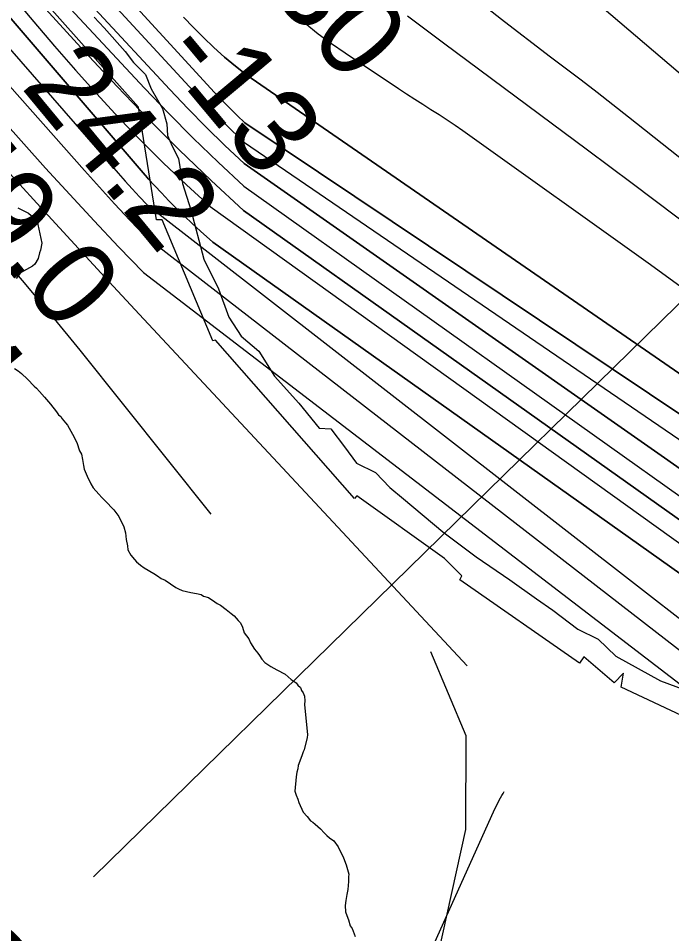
# Model space of a CAD drawing. Extents: x 3172231 to 3210228, y 940198 to 965780.
# Drawn here: x 3190904 to 3191420, y 947104 to 947827 of the extents above; entities that cross this region are included whole.
import ezdxf

# ---------------------------------------------------------------- set-up
doc = ezdxf.new("R2010")
doc.units = 0
for name, color, linetype in [('V-RIVR-EDGE', 7, 'Continuous'), ('V-RIVR-RANG', 7, 'Continuous'), ('V-RIVR-RANG-IDEN', 7, 'Continuous'), ('V-ROAD-CNTR', 7, 'Continuous'), ('V-RRAP-RVMT', 7, 'Continuous'), ('V-SITE-VEGE', 7, 'Continuous'), ('V-TOPO-DPTH', 7, 'Continuous'), ('V-TOPO-MAJR', 7, 'Continuous'), ('V-TOPO-MINR', 7, 'Continuous'), ('V-TOPO-SHOR', 7, 'Continuous'), ('V-TOPO-WATR', 7, 'Continuous')]:
    doc.layers.add(name, color=color, linetype=linetype)

msp = doc.modelspace()

# ---------------------------------------------------------------- linework, layer by layer
at = {"layer": 'V-RIVR-EDGE'}
msp.add_lwpolyline([(3190963.675, 947827.885), (3190971.434, 947819.568), (3190987.984, 947800.857), (3190994.704, 947792.023), (3191004.016, 947782.665), (3191008.656, 947771.244), (3191017.434, 947755.664), (3191021.034, 947743.726), (3191021.53, 947734.39), (3191025.14, 947726.083), (3191030.302, 947716.216), (3191033.365, 947696.501), (3191040.055, 947675.74), (3191050.332, 947636.818), (3191061.684, 947613.452), (3191069.926, 947591.13), (3191079.743, 947576.066), (3191093.716, 947564.103), (3191106.114, 947544.365), (3191125.251, 947523.054), (3191141.279, 947503.307), (3191150.613, 947502.765), (3191161.469, 947488.735), (3191170.772, 947475.747), (3191185.794, 947468.449), (3191197.175, 947456.492), (3191208.044, 947447.649), (3191239.097, 947421.641), (3191265.498, 947401.868), (3191291.902, 947383.651), (3191313.129, 947368.558), (3191326.072, 947359.71), (3191345.743, 947344.621), (3191361.801, 947336.802), (3191375.77, 947323.283), (3191410.989, 947304.007), (3191430.16, 947296.699)], dxfattribs=at)
at = {"layer": 'V-RIVR-RANG'}
msp.add_line((3190962.933, 947149.209), (3191771.579, 947939.938), dxfattribs=at)
at = {"layer": 'V-ROAD-CNTR'}
msp.add_lwpolyline([(3191038.305, 946665.928), (3191279.107, 947200.55), (3191279.971, 947202.406), (3191280.86, 947204.251), (3191281.776, 947206.084), (3191282.716, 947207.905), (3191283.682, 947209.713), (3191284.673, 947211.509), (3191285.689, 947213.291), (3191286.73, 947215.058), (3191287.616, 947216.523)], dxfattribs=at)
at = {"layer": 'V-RRAP-RVMT'}
for p, q in [((3190998.585, 947756.725), (3190913.183, 947852.785)), ((3191012.785, 947667.841), (3190998.585, 947756.725)), ((3191017.206, 947667.92), (3191012.785, 947667.841)), ((3191057.359, 947572.274), (3191017.206, 947667.92)), ((3191059.556, 947572.991), (3191057.359, 947572.274)), ((3191169.285, 947447.752), (3191059.556, 947572.991)), ((3191171.22, 947449.949), (3191169.285, 947447.752)), ((3191240.29, 947400.509), (3191171.22, 947449.949)), ((3191254.065, 947386.827), (3191240.29, 947400.509)), ((3191252.577, 947383.56), (3191254.065, 947386.827)), ((3191347.149, 947317.821), (3191252.577, 947383.56)), ((3191350.507, 947322.991), (3191347.149, 947317.821)), ((3191374.555, 947302.305), (3191350.507, 947322.991)), ((3191381.916, 947309.92), (3191374.555, 947302.305)), ((3191379.902, 947299.004), (3191381.916, 947309.92)), ((3191508.358, 947238.465), (3191379.902, 947299.004))]:
    msp.add_line(p, q, dxfattribs=at)
at = {"layer": 'V-SITE-VEGE'}
for p, q in [((3190903.338, 947677.339), (3190911.675, 947673.106)), ((3190911.675, 947673.106), (3190913.834, 947671.222)), ((3190913.834, 947671.222), (3190916.341, 947668.594)), ((3190916.341, 947668.594), (3190919.171, 947664.125)), ((3190919.171, 947664.125), (3190921.477, 947653.064)), ((3190922.124, 947649.382), (3190921.262, 947643.897)), ((3190921.477, 947653.064), (3190922.124, 947649.382)), ((3190920.478, 947641.714), (3190919.275, 947637.34)), ((3190921.262, 947643.897), (3190920.478, 947641.714)), ((3190916.605, 947632.998), (3190914.727, 947631.208)), ((3190919.275, 947637.34), (3190916.605, 947632.998)), ((3190905.431, 947625.926), (3190902.027, 947621.603)), ((3190914.727, 947631.208), (3190905.431, 947625.926)), ((3190900.723, 947550.457), (3190903.612, 947548.555)), ((3190903.612, 947548.555), (3190906.136, 947546.66)), ((3190906.136, 947546.66), (3190910.801, 947542.148)), ((3190910.801, 947542.148), (3190916.171, 947536.519)), ((3190916.171, 947536.519), (3190917.971, 947535.007)), ((3190917.971, 947535.007), (3190920.476, 947532.382)), ((3190920.476, 947532.382), (3190924.408, 947527.886)), ((3190924.408, 947527.886), (3190929.044, 947522.277)), ((3190929.044, 947522.277), (3190933.673, 947516.295)), ((3190933.673, 947516.295), (3190935.455, 947514.052)), ((3190935.455, 947514.052), (3190937.257, 947512.543)), ((3190937.257, 947512.543), (3190938.312, 947510.683)), ((3190938.312, 947510.683), (3190940.808, 947507.689)), ((3190940.808, 947507.689), (3190942.598, 947505.813)), ((3190942.598, 947505.813), (3190946.469, 947498.751)), ((3190946.469, 947498.751), (3190949.981, 947492.065)), ((3190949.981, 947492.065), (3190952.025, 947485.413)), ((3190952.025, 947485.413), (3190953.432, 947482.812)), ((3190953.432, 947482.812), (3190954.438, 947478.753)), ((3190954.438, 947478.753), (3190955.06, 947473.964)), ((3190955.06, 947473.964), (3190955.724, 947471.017)), ((3190955.724, 947471.017), (3190958.161, 947465.457)), ((3190958.161, 947465.457), (3190960.956, 947459.52)), ((3190960.956, 947459.52), (3190962.712, 947456.178)), ((3190962.712, 947456.178), (3190967.367, 947451.297)), ((3190967.367, 947451.297), (3190969.507, 947448.68)), ((3190969.507, 947448.68), (3190972.38, 947446.044)), ((3190972.38, 947446.044), (3190979.182, 947438.913)), ((3190979.182, 947438.913), (3190983.095, 947433.684)), ((3190983.095, 947433.684), (3190984.834, 947429.609)), ((3190984.834, 947429.609), (3190985.895, 947427.749)), ((3190985.895, 947427.749), (3190986.939, 947425.523)), ((3190986.939, 947425.523), (3190988.295, 947420.72)), ((3190988.295, 947420.72), (3190988.907, 947415.57)), ((3190988.907, 947415.57), (3190989.886, 947410.411)), ((3190989.886, 947410.411), (3190990.185, 947407.47)), ((3190990.185, 947407.47), (3190992.647, 947403.007)), ((3190992.647, 947403.007), (3190995.504, 947399.638)), ((3190995.504, 947399.638), (3190996.925, 947397.771)), ((3190996.925, 947397.771), (3191000.167, 947395.127)), ((3191000.167, 947395.127), (3191003.057, 947393.224)), ((3191003.057, 947393.224), (3191010.655, 947388.643)), ((3191010.655, 947388.643), (3191013.547, 947386.742)), ((3191013.547, 947386.742), (3191016.437, 947384.837)), ((3191016.437, 947384.837), (3191019.701, 947383.293)), ((3191019.701, 947383.293), (3191028.006, 947377.596)), ((3191028.006, 947377.596), (3191030.181, 947376.445)), ((3191030.181, 947376.445), (3191033.089, 947375.275)), ((3191033.089, 947375.275), (3191040.021, 947373.643)), ((3191040.021, 947373.643), (3191044.404, 947372.808)), ((3191044.404, 947372.808), (3191048.054, 947371.988)), ((3191048.054, 947371.988), (3191049.86, 947370.848)), ((3191049.86, 947370.848), (3191053.868, 947369.65)), ((3191053.868, 947369.65), (3191058.924, 947366.229)), ((3191058.924, 947366.229), (3191060.733, 947365.087)), ((3191060.733, 947365.087), (3191063.264, 947363.559)), ((3191063.264, 947363.559), (3191067.954, 947360.147)), ((3191067.954, 947360.147), (3191071.919, 947357.12)), ((3191071.919, 947357.12), (3191074.076, 947355.234)), ((3191074.076, 947355.234), (3191077.291, 947351.49)), ((3191077.291, 947351.49), (3191079.081, 947349.612)), ((3191079.081, 947349.612), (3191080.836, 947346.27)), ((3191080.836, 947346.27), (3191082.2, 947341.836)), ((3191082.2, 947341.836), (3191085.753, 947336.982)), ((3191085.753, 947336.982), (3191087.152, 947334.012)), ((3191087.152, 947334.012), (3191090.333, 947328.802)), ((3191090.333, 947328.802), (3191092.831, 947325.808)), ((3191092.831, 947325.808), (3191094.252, 947323.94)), ((3191094.252, 947323.94), (3191096.018, 947320.964)), ((3191096.018, 947320.964), (3191098.527, 947318.337)), ((3191098.527, 947318.337), (3191103.223, 947315.292)), ((3191103.223, 947315.292), (3191107.929, 947312.613)), ((3191107.929, 947312.613), (3191114.452, 947309.158)), ((3191114.452, 947309.158), (3191119.123, 947305.013)), ((3191119.123, 947305.013), (3191123.099, 947302.35)), ((3191123.099, 947302.35), (3191124.52, 947300.482)), ((3191124.52, 947300.482), (3191126.674, 947298.596)), ((3191126.674, 947298.596), (3191127.358, 947296.38)), ((3191127.358, 947296.38), (3191128.784, 947294.512)), ((3191128.784, 947294.512), (3191129.822, 947291.92)), ((3191130.103, 947288.242), (3191129.667, 947285.319)), ((3191129.667, 947285.319), (3191132.04, 947261.415)), ((3191129.822, 947291.92), (3191130.103, 947288.242)), ((3191131.989, 947259.215), (3191129.556, 947249.366)), ((3191132.04, 947261.415), (3191131.989, 947259.215)), ((3191129.556, 947249.366), (3191128.788, 947247.916)), ((3191127.61, 947244.642), (3191124.864, 947237.003)), ((3191128.788, 947247.916), (3191127.61, 947244.642)), ((3191124.436, 947234.445), (3191123.641, 947231.895)), ((3191124.864, 947237.003), (3191124.436, 947234.445)), ((3191123.191, 947228.235), (3191122.189, 947216.885)), ((3191123.641, 947231.895), (3191123.191, 947228.235)), ((3191122.189, 947216.885), (3191123.211, 947213.559)), ((3191123.211, 947213.559), (3191124.61, 947210.592)), ((3191124.61, 947210.592), (3191125.282, 947208.007)), ((3191125.282, 947208.007), (3191128.767, 947200.223)), ((3191128.767, 947200.223), (3191131.991, 947196.841)), ((3191131.991, 947196.841), (3191134.479, 947193.483)), ((3191134.479, 947193.483), (3191136.288, 947192.342)), ((3191136.288, 947192.342), (3191138.088, 947190.83)), ((3191138.088, 947190.83), (3191142.401, 947187.06)), ((3191142.401, 947187.06), (3191145.264, 947184.058)), ((3191145.264, 947184.058), (3191147.414, 947181.807)), ((3191147.414, 947181.807), (3191149.571, 947179.921)), ((3191149.571, 947179.921), (3191152.819, 947177.643)), ((3191152.819, 947177.643), (3191156.374, 947172.79)), ((3191156.374, 947172.79), (3191160.577, 947164.254)), ((3191160.577, 947164.254), (3191162.648, 947158.701)), ((3191162.648, 947158.701), (3191164.675, 947151.314)), ((3191164.624, 947149.115), (3191164.538, 947145.449)), ((3191164.675, 947151.314), (3191164.624, 947149.115)), ((3191164.538, 947145.449), (3191164.024, 947139.223)), ((3191163.196, 947135.207), (3191162.351, 947130.457)), ((3191164.024, 947139.223), (3191163.196, 947135.207)), ((3191162.351, 947130.457), (3191161.89, 947126.431)), ((3191161.89, 947126.431), (3191162.144, 947121.657)), ((3191162.144, 947121.657), (3191163.174, 947118.698)), ((3191163.174, 947118.698), (3191164.564, 947115.364)), ((3191164.564, 947115.364), (3191165.918, 947110.561)), ((3191165.918, 947110.561), (3191167.333, 947108.327)), ((3191167.333, 947108.327), (3191169.754, 947102.033))]:
    msp.add_line(p, q, dxfattribs=at)
at = {"layer": 'V-TOPO-DPTH'}
for points in [[(3191975.853, 946999.192), (3191057.366, 947650.198), (3191047.698, 947658.964), (3191041.097, 947664.995), (3191034.835, 947670.857), (3191028.67, 947676.816), (3191022.65, 947682.921), (3191016.726, 947689.124), (3191006.307, 947700.299), (3191005.67, 947700.991), (3191003.798, 947703.104), (3190371.389, 948440.144)], [(3190795.989, 948054.391), (3191058.755, 947768.507), (3191064.568, 947762.315), (3191070.468, 947756.208), (3191076.496, 947750.229), (3191082.61, 947744.334), (3191635.142, 947374.634), (3191679.916, 947341.25), (3191724.064, 947307.079), (3191767.273, 947271.729), (3191809.857, 947235.592), (3192012.278, 947059.062), (3192038.925, 947035.354), (3192065.252, 947011.301), (3192091.097, 946986.732), (3192116.621, 946961.819), (3192125.015, 946953.462)], [(3192125.015, 946953.462), (3192116.621, 946961.819), (3192091.097, 946986.732), (3192065.252, 947011.301), (3192038.925, 947035.354), (3192012.278, 947059.062), (3191809.857, 947235.592), (3191767.273, 947271.729), (3191724.064, 947307.079), (3191679.916, 947341.25), (3191635.142, 947374.634), (3191082.61, 947744.334), (3191076.496, 947750.229), (3191070.468, 947756.208), (3191064.568, 947762.315), (3191058.755, 947768.507), (3190795.989, 948054.391)], [(3192105.596, 946941.56), (3192084.673, 946962.391), (3192067.073, 946979.569), (3192049.253, 946996.51), (3192031.1, 947013.095), (3192012.726, 947029.442), (3191871.98, 947152.187), (3191843.196, 947176.588), (3191813.973, 947200.437), (3191784.094, 947223.457), (3191753.777, 947245.924), (3191722.828, 947267.51), (3191691.477, 947288.475), (3191659.523, 947308.509), (3191081.962, 947712.367), (3191066.909, 947726.551), (3191052.087, 947740.967), (3191037.61, 947755.73), (3191023.364, 947770.724), (3190904.893, 947898.407)], [(3190904.893, 947898.407), (3191023.364, 947770.724), (3191037.61, 947755.73), (3191052.087, 947740.967), (3191066.909, 947726.551), (3191081.962, 947712.367), (3191659.523, 947308.509), (3191691.477, 947288.475), (3191722.828, 947267.51), (3191753.777, 947245.924), (3191784.094, 947223.457), (3191813.973, 947200.437), (3191843.196, 947176.588), (3191871.98, 947152.187), (3192012.726, 947029.442), (3192031.1, 947013.095), (3192049.253, 946996.51), (3192067.073, 946979.569), (3192084.673, 946962.391), (3192105.596, 946941.56)], [(3192074.996, 946940.791), (3192052.727, 946962.962), (3192043.051, 946972.406), (3192033.254, 946981.719), (3192023.275, 946990.837), (3192013.173, 946999.824), (3191935.175, 947067.846), (3191919.66, 947080.985), (3191903.9, 947093.815), (3191887.774, 947106.182), (3191871.403, 947118.239), (3191854.676, 947129.792), (3191837.719, 947140.985), (3191820.416, 947151.636), (3191081.606, 947675.34), (3191055.894, 947699.044), (3191030.612, 947723.186), (3191005.973, 947747.984), (3190981.764, 947773.22), (3190956.043, 947800.747), (3190919.634, 947840.373)], [(3190919.634, 947840.373), (3190956.043, 947800.747), (3190981.764, 947773.22), (3191005.973, 947747.984), (3191030.612, 947723.186), (3191055.894, 947699.044), (3191081.606, 947675.34), (3191820.416, 947151.636), (3191837.719, 947140.985), (3191854.676, 947129.792), (3191871.403, 947118.239), (3191887.774, 947106.182), (3191903.9, 947093.815), (3191919.66, 947080.985), (3191935.175, 947067.846), (3192013.173, 946999.824), (3192023.275, 946990.837), (3192033.254, 946981.719), (3192043.051, 946972.406), (3192052.727, 946962.962), (3192074.996, 946940.791)], [(3191034.173, 947827.902), (3191041.949, 947819.8), (3191049.938, 947811.772), (3191058.11, 947803.943), (3191066.559, 947796.413), (3191075.192, 947789.082), (3191084.105, 947782.101), (3191748.04, 947324.383), (3192006.622, 947110.179), (3192014.989, 947103.225), (3192023.341, 947096.252), (3192031.67, 947089.253), (3192039.983, 947082.235), (3192048.29, 947075.208), (3192056.601, 947068.187), (3192064.921, 947061.176), (3192073.246, 947054.171), (3192086.789, 947042.788), (3192090.015, 947040.073), (3192093.24, 947037.357), (3192096.461, 947034.637), (3192099.681, 947031.915), (3192938.779, 946321.755)], [(3192938.779, 946321.755), (3192099.681, 947031.915), (3192096.461, 947034.637), (3192093.24, 947037.357), (3192090.015, 947040.073), (3192086.789, 947042.788), (3192073.246, 947054.171), (3192064.921, 947061.176), (3192056.601, 947068.187), (3192048.29, 947075.208), (3192039.983, 947082.235), (3192031.67, 947089.253), (3192023.341, 947096.252), (3192014.989, 947103.225), (3192006.622, 947110.179), (3191748.04, 947324.383), (3191084.105, 947782.101), (3191075.192, 947789.082), (3191066.559, 947796.413), (3191058.11, 947803.943), (3191049.938, 947811.772), (3191041.949, 947819.8), (3191034.173, 947827.902)], [(3191120.419, 947831.465), (3191130.389, 947823.002), (3191140.576, 947814.822), (3191151.091, 947807.068), (3191161.824, 947799.597), (3191204.13, 947771.425), (3191210.47, 947767.251), (3191216.839, 947763.122), (3191223.251, 947759.062), (3191229.693, 947755.046), (3191236.113, 947751), (3191242.477, 947746.869), (3191248.755, 947742.609), (3191254.977, 947738.263), (3191403.088, 947632.554), (3191467.814, 947585.565)], [(3191120.419, 947831.465), (3191130.389, 947823.002), (3191140.576, 947814.822), (3191151.091, 947807.068), (3191161.824, 947799.597), (3191204.13, 947771.425), (3191210.47, 947767.251), (3191216.839, 947763.122), (3191223.251, 947759.062), (3191229.693, 947755.046), (3191236.113, 947751), (3191242.477, 947746.869), (3191248.755, 947742.609), (3191254.977, 947738.263), (3191403.088, 947632.554), (3191467.814, 947585.565)]]:
    msp.add_lwpolyline(points, dxfattribs=at)
at = {"layer": 'V-TOPO-MAJR'}
for points in [[(3190780.826, 947870.291), (3190841.33, 947802.226), (3190925.193, 947708.779), (3190944.226, 947687.848), (3190963.438, 947667.086), (3190982.921, 947646.576), (3191002.583, 947626.236), (3191916.297, 946926.02), (3191939.622, 946908.908), (3191943.668, 946905.677), (3191947.52, 946902.246), (3191951.081, 946898.512), (3191954.447, 946894.578), (3191965.03, 946881.133)], [(3192112.75, 947104.696), (3192085.094, 947128.316), (3191933.046, 947258.17), (3191872.227, 947309.714), (3191811.151, 947360.95), (3191749.689, 947411.721), (3191687.97, 947462.184), (3191632.721, 947507.009), (3191598.329, 947534.696), (3191563.798, 947562.207), (3191529.059, 947589.454), (3191494.182, 947616.526), (3191459.126, 947643.368), (3191423.974, 947670.082), (3191388.674, 947696.601), (3191353.277, 947722.992), (3191239.467, 947807.355), (3191211.089, 947828.544)]]:
    msp.add_lwpolyline(points, dxfattribs=at)
at = {"layer": 'V-TOPO-MINR'}
for points in [[(3189654.756, 949405.366), (3190276.246, 948537.001), (3190281.623, 948529.611), (3190287.075, 948522.279), (3190292.642, 948515.033), (3190298.284, 948507.844), (3190380.452, 948404.824), (3190427.618, 948346.486), (3190475.293, 948288.575), (3190523.733, 948231.301), (3190572.682, 948174.452), (3190982.548, 947704.784), (3190988.103, 947698.499), (3190993.711, 947692.263), (3190999.397, 947686.099), (3191005.137, 947679.982), (3191821.886, 947045.773), (3191936.602, 946961.604), (3191956.768, 946945.504), (3191975.964, 946928.401), (3191993.708, 946909.795), (3192010.483, 946890.186), (3192012.814, 946887.224)], [(3189271.701, 949283.317), (3190177.18, 948464.824), (3190189.741, 948449.425), (3190202.355, 948434.07), (3190215.004, 948418.744), (3190349.973, 948255.782), (3190430.715, 948159.499), (3190512.233, 948063.886), (3190594.915, 947969.277), (3190678.373, 947875.339), (3190859.895, 947673.523), (3190883.501, 947646.818), (3190906.794, 947619.848), (3190929.619, 947592.48), (3190952.131, 947564.847), (3191055.723, 947435.429)], [(3189726.179, 949118.6), (3190220.44, 948473.312), (3190220.888, 948472.734), (3190221.342, 948472.162), (3190224.465, 948468.273), (3190226.272, 948466.057), (3190228.1, 948463.86), (3190229.961, 948461.69), (3190231.843, 948459.538), (3190243.425, 948446.5), (3190251.107, 948437.837), (3190258.778, 948429.164), (3190266.435, 948420.478), (3190274.081, 948411.783), (3190785.394, 947829.287), (3190811.718, 947799.441), (3190838.135, 947769.678), (3190864.693, 947740.041), (3190891.344, 947710.487), (3190918.132, 947681.057), (3190945.008, 947651.708), (3190972.017, 947622.481), (3190999.115, 947593.336), (3191258.344, 947315.778)], [(3190343.998, 948500.758), (3190915.826, 947824.144), (3190932.254, 947805.005), (3190948.874, 947786.037), (3190965.783, 947767.326), (3190982.885, 947748.786), (3191000.375, 947730.625), (3191018.19, 947712.798), (3191036.492, 947695.472), (3191055.119, 947678.48), (3191889.718, 947080.147)], [(3190371.389, 948440.144), (3191003.798, 947703.104), (3191005.67, 947700.991), (3191006.307, 947700.299), (3191016.726, 947689.124), (3191022.65, 947682.921), (3191028.67, 947676.816), (3191034.835, 947670.857), (3191041.097, 947664.995), (3191047.698, 947658.964), (3191057.366, 947650.198), (3191975.853, 946999.192)], [(3190795.989, 948054.391), (3191058.755, 947768.507), (3191064.568, 947762.315), (3191070.468, 947756.208), (3191076.496, 947750.229), (3191082.61, 947744.334), (3191635.142, 947374.634), (3191679.916, 947341.25), (3191724.064, 947307.079), (3191767.273, 947271.729), (3191809.857, 947235.592), (3192012.278, 947059.062), (3192038.925, 947035.354), (3192065.252, 947011.301), (3192091.097, 946986.732), (3192116.621, 946961.819), (3192125.015, 946953.462)], [(3190880.337, 947944.43), (3191041.855, 947769.581), (3191051.689, 947759.172), (3191061.675, 947748.915), (3191071.889, 947738.884), (3191082.254, 947729.005), (3191650.711, 947341.141), (3191683.208, 947318.366), (3191694.589, 947310.147), (3191732.069, 947282.287), (3191769.016, 947253.755), (3191805.164, 947224.218), (3191840.779, 947194.01), (3192012.502, 947044.249), (3192035.012, 947024.222), (3192057.251, 947003.904), (3192079.083, 946983.15), (3192100.643, 946962.105), (3192107.839, 946954.941)], [(3190769.795, 947916.905), (3190955.962, 947706.712), (3190967.744, 947693.583), (3190979.637, 947680.557), (3190991.699, 947667.687), (3191003.873, 947654.92), (3191863.674, 946989.558), (3191868.763, 946986.139), (3191938.112, 946935.255), (3191950.218, 946925.59), (3191961.742, 946915.323), (3191972.393, 946904.153), (3191982.463, 946892.382), (3191992.769, 946879.29)], [(3190904.893, 947898.407), (3191023.364, 947770.724), (3191037.61, 947755.73), (3191052.087, 947740.967), (3191066.909, 947726.551), (3191081.962, 947712.367), (3191659.523, 947308.509), (3191691.477, 947288.475), (3191722.828, 947267.51), (3191753.777, 947245.924), (3191784.094, 947223.457), (3191813.973, 947200.437), (3191843.196, 947176.588), (3191871.98, 947152.187), (3192012.726, 947029.442), (3192031.1, 947013.095), (3192049.253, 946996.51), (3192067.073, 946979.569), (3192084.673, 946962.391), (3192105.596, 946941.56)], [(3191313.374, 947879.998), (3191463.893, 947751.654), (3191503.511, 947718.45), (3191543.496, 947685.703), (3191584.032, 947653.64), (3191624.936, 947622.034), (3191666.188, 947590.868), (3191707.535, 947559.83), (3191749.028, 947528.986), (3191790.617, 947498.27), (3191797.26, 947493.388), (3191841.742, 947459.711), (3191885.559, 947425.213), (3191928.377, 947389.482), (3191970.529, 947352.931), (3192178.808, 947167.071)], [(3191237.421, 947864.246), (3191285.532, 947826.414), (3191298, 947816.68), (3191310.513, 947807.003), (3191323.092, 947797.414), (3191335.716, 947787.882), (3191348.335, 947778.344), (3191360.902, 947768.738), (3191373.39, 947759.031), (3191385.827, 947749.256), (3191525.002, 947638.957), (3191606.573, 947573.482), (3191687.593, 947507.339), (3191767.786, 947440.196), (3191847.426, 947372.385), (3192135.776, 947123.763)], [(3190930.078, 947850.58), (3191003.325, 947771.936), (3191022.365, 947751.998), (3191041.728, 947732.386), (3191061.574, 947713.264), (3191081.742, 947694.468), (3191715.374, 947244.512), (3191740.266, 947229.738), (3191764.84, 947214.47), (3191788.937, 947198.459), (3191812.715, 947181.953), (3191835.998, 947164.751), (3191858.94, 947147.118), (3191881.368, 947128.836), (3191903.455, 947110.123), (3192012.949, 947014.633), (3192027.187, 947001.966), (3192041.254, 946989.115), (3192055.063, 946975.988), (3192068.701, 946962.676), (3192090.281, 946941.191)], [(3191034.173, 947827.902), (3191041.949, 947819.8), (3191049.938, 947811.772), (3191058.11, 947803.943), (3191066.559, 947796.413), (3191075.192, 947789.082), (3191084.105, 947782.101), (3191748.04, 947324.383), (3192006.622, 947110.179), (3192014.989, 947103.225), (3192023.341, 947096.252), (3192031.67, 947089.253), (3192039.983, 947082.235), (3192048.29, 947075.208), (3192056.601, 947068.187), (3192064.921, 947061.176), (3192073.246, 947054.171), (3192086.789, 947042.788), (3192090.015, 947040.073), (3192093.24, 947037.357), (3192096.461, 947034.637), (3192099.681, 947031.915), (3192938.779, 946321.755)], [(3191120.419, 947831.465), (3191130.389, 947823.002), (3191140.576, 947814.822), (3191151.091, 947807.068), (3191161.824, 947799.597), (3191204.13, 947771.425), (3191210.47, 947767.251), (3191216.839, 947763.122), (3191223.251, 947759.062), (3191229.693, 947755.046), (3191236.113, 947751), (3191242.477, 947746.869), (3191248.755, 947742.609), (3191254.977, 947738.263), (3191403.088, 947632.554), (3191467.814, 947585.565)]]:
    msp.add_lwpolyline(points, dxfattribs=at)
at = {"layer": 'V-TOPO-SHOR'}
msp.add_lwpolyline([(3190486.843, 945694.168), (3190609.066, 945794.06), (3190665.881, 945867.977), (3191073.212, 946755.656), (3191235.213, 947086.334), (3191257.242, 947186.475), (3191257.425, 947260.532), (3191229.599, 947326.906)], dxfattribs=at)
at = {"layer": 'V-TOPO-WATR'}
msp.add_lwpolyline([(3190919.634, 947840.373), (3190956.043, 947800.747), (3190981.764, 947773.22), (3191005.973, 947747.984), (3191030.612, 947723.186), (3191055.894, 947699.044), (3191081.606, 947675.34), (3191820.416, 947151.636), (3191837.719, 947140.985), (3191854.676, 947129.792), (3191871.403, 947118.239), (3191887.774, 947106.182), (3191903.9, 947093.815), (3191919.66, 947080.985), (3191935.175, 947067.846), (3192013.173, 946999.824), (3192023.275, 946990.837), (3192033.254, 946981.719), (3192043.051, 946972.406), (3192052.727, 946962.962), (3192074.996, 946940.791)], dxfattribs=at)

# ---------------------------------------------------------------- texts
at = {"layer": 'V-RIVR-RANG'}
for s, rotation, p in [('-30', 309.871667, (3191081.34, 947872.962)), ('-13', 309.871667, (3191014.14, 947797.426)), ('24.2', 309.648326, (3190904.936, 947772.896)), ('49.0', 309.648326, (3190826.246, 947711.132)), ('54.4', 309.648326, (3190751.258, 947644.9))]:
    msp.add_text(s, height=67, rotation=rotation, dxfattribs=at).set_placement(p)
at = {"layer": 'V-RIVR-RANG-IDEN'}
msp.add_text('D-10', height=83, rotation=44.753602, dxfattribs=at).set_placement((3190764.342, 946906.769))

doc.saveas('drawing.dxf')
